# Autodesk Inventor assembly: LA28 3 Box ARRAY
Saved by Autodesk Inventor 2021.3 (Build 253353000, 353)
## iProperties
Created: 2023-01
Part Number: LA28 3 Box ARRAY
Document SubType Name: Assembly
Designer: AdminForWorker
Title: LA28 3 Box ARRAY v2
Author: AdminForWorker
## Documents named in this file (3)
- c:\worker\convert-fusion-r08-cosv3\tmp\job-1\7\output\files\23b6ab5d-c720-4e55-9879-a23ce6995bc1\3ff1bef2-032f-42cc-bf09-fa64feb3e8f5.iam
- c:\worker\convert-fusion-r08-cosv3\tmp\job-1\7\output\files\23b6ab5d-c720-4e55-9879-a23ce6995bc1\LA28 RF1 Sheet Metal Assembly v3.iam
- c:\worker\convert-fusion-r08-cosv3\tmp\job-1\7\output\files\23b6ab5d-c720-4e55-9879-a23ce6995bc1\LA28 TOUR BLOCK v2.ipt
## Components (4 placed, 2 different names)
1. LA28 RF1 Sheet Metal Assembly v3:1 [sub-assembly]
2. LA28 TOUR BLOCK v2:1
3. LA28 TOUR BLOCK v2:2
4. LA28 TOUR BLOCK v2:3
